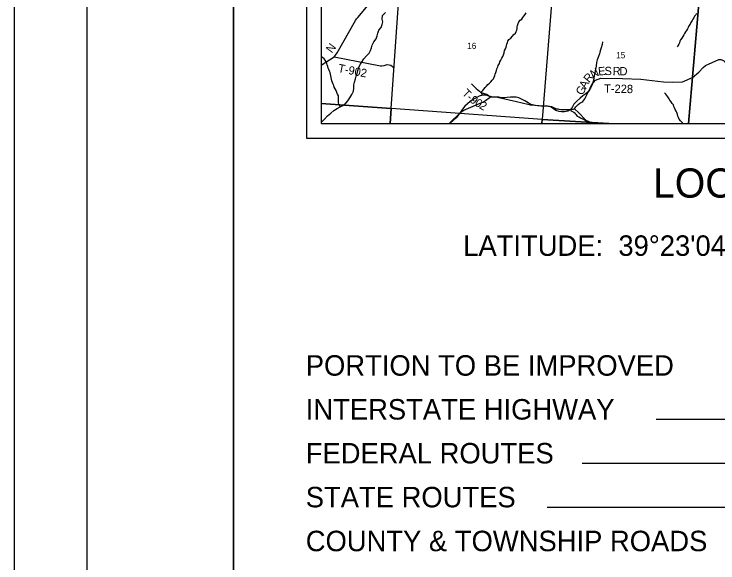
# Model space of a CAD drawing. Extents: x -13.1 to 43.1, y 0 to 22.
# Drawn here: x 0 to 4.813, y 11.097 to 14.849 of the extents above; entities that cross this region are included whole.
import ezdxf

# ---------------------------------------------------------------- set-up
doc = ezdxf.new("R2010")
doc.units = 0
for name, color, linetype in [('GM_X_Corporation', 7, 'Continuous'), ('GM_X_County_Road', 7, 'Continuous'), ('GM_X_County_Road_Text', 7, 'Continuous'), ('GM_X_Minor_River', 7, 'Continuous'), ('GM_X_Section_Text', 7, 'Continuous'), ('GM_X_Township_Road', 7, 'Continuous'), ('GM_X_Township_Road_Text', 7, 'Continuous'), ('SH_Border', 7, 'Continuous'), ('SH_Data', 7, 'Continuous'), ('SH_Text', 7, 'Continuous')]:
    doc.layers.add(name, color=color, linetype=linetype)

msp = doc.modelspace()

# ---------------------------------------------------------------- linework, layer by layer
at = {"layer": 'GM_X_Corporation'}
for points in [[(7.0807, 20.9), (2.1, 20.9), (2.1, 14.1), (6.6193, 14.1), (6.6994, 15.2069), (6.7531, 15.956), (6.8236, 16.9075), (6.9509, 19.0179), (7.0108, 19.8446), (7.0164, 19.8954), (7.0617, 20.6133)], [(7.0804, 20.9), (2.1, 20.9), (2.1, 14.1), (6.619, 14.1), (6.6992, 15.2074), (6.7528, 15.9566), (6.8234, 16.908), (6.8365, 17.1257), (6.9507, 19.0184), (6.9616, 19.1692), (7.0106, 19.8452), (7.0162, 19.896), (7.0615, 20.6138)], [(2.1, 17.2152), (2.1, 14.1), (6.619, 14.1), (6.6992, 15.2074), (6.7528, 15.9566), (6.8234, 16.908), (4.4304, 17.0575), (3.8328, 17.0966), (2.8442, 17.1637), (2.1437, 17.2135)], [(2.1, 15.1883), (2.1, 14.2382), (2.5786, 14.2031), (2.6447, 15.1518)], [(2.6447, 15.1518), (3.6885, 15.0891), (3.6113, 14.1287), (2.5786, 14.2031)], [(4.0665, 14.1), (4.6107, 14.1), (4.6921, 15.0289), (3.6885, 15.0891), (3.6113, 14.1287)], [(4.6107, 14.1), (5.5941, 14.1), (5.6613, 14.9873), (4.6921, 15.0289)], [(2.1, 14.2382), (2.1, 14.1), (2.5718, 14.1), (2.5786, 14.2031)], [(2.5718, 14.1), (3.6092, 14.1), (3.6113, 14.1287), (2.5786, 14.2031)], [(3.6092, 14.1), (4.0665, 14.1), (3.6113, 14.1287)]]:
    msp.add_lwpolyline(points, close=True, dxfattribs=at)
at = {"layer": 'GM_X_County_Road'}
msp.add_lwpolyline([(2.1, 14.4999), (2.188, 14.5566), (2.1915, 14.5592), (2.1978, 14.5682), (2.2084, 14.5828), (2.3353, 14.8038), (2.342, 14.8155), (2.3498, 14.8244), (2.4327, 14.9227)], dxfattribs=at)
at = {"layer": 'GM_X_Minor_River'}
for points in [[(2.1, 14.107), (2.1006, 14.1077), (2.1198, 14.1281), (2.1427, 14.1531), (2.1649, 14.1719), (2.1855, 14.1893), (2.2099, 14.2044), (2.2305, 14.2141), (2.2488, 14.2247), (2.2679, 14.239), (2.2832, 14.2564), (2.2947, 14.2753), (2.3093, 14.2995), (2.3201, 14.3207), (2.324, 14.3412), (2.3226, 14.3647), (2.3273, 14.3829), (2.335, 14.4064), (2.3397, 14.4239), (2.3451, 14.4428), (2.3513, 14.4633), (2.3583, 14.4868), (2.3698, 14.5072), (2.3805, 14.5246), (2.3913, 14.5428), (2.4089, 14.5632), (2.428, 14.5806), (2.438, 14.6002), (2.4441, 14.6177), (2.4496, 14.6366), (2.4603, 14.6586), (2.4764, 14.6805), (2.4826, 14.7002), (2.4873, 14.7192), (2.4942, 14.7381), (2.5103, 14.7563), (2.518, 14.7775), (2.5204, 14.7949), (2.5167, 14.8147), (2.5191, 14.8397), (2.539, 14.8601)], [(3.2021, 14.2935), (3.1931, 14.3153), (3.205, 14.3254), (3.2131, 14.3352), (3.2212, 14.3461), (3.2304, 14.3558), (3.2401, 14.3671), (3.2505, 14.3776), (3.2601, 14.3866), (3.2701, 14.3963), (3.2778, 14.4061), (3.2825, 14.4167), (3.2876, 14.4284), (3.2904, 14.4386), (3.2947, 14.4499), (3.2994, 14.462), (3.3014, 14.4745), (3.3077, 14.4874), (3.3112, 14.498), (3.3182, 14.5112), (3.3226, 14.5229), (3.3276, 14.5334), (3.3354, 14.5463), (3.3412, 14.5583), (3.3456, 14.5712), (3.3503, 14.584), (3.3539, 14.5996), (3.3597, 14.6113), (3.3652, 14.6237), (3.3661, 14.634), (3.3693, 14.6442), (3.3728, 14.654), (3.3771, 14.6638), (3.3837, 14.6747), (3.3956, 14.6852), (3.4049, 14.6965), (3.4179, 14.7089), (3.4291, 14.7193), (3.4322, 14.7292), (3.4369, 14.7398), (3.4397, 14.7511), (3.441, 14.761), (3.4415, 14.7716), (3.4462, 14.7841), (3.4517, 14.7958), (3.4605, 14.8063), (3.4713, 14.8149), (3.4779, 14.8251), (3.4856, 14.8348), (3.4945, 14.8453), (3.5014, 14.8563)], [(4.6666, 14.8538), (4.6612, 14.844), (4.6535, 14.8343), (4.6477, 14.8241), (4.6418, 14.8143), (4.6356, 14.8045), (4.6283, 14.7917), (4.6224, 14.7807), (4.6139, 14.7679), (4.6088, 14.7574), (4.6038, 14.7475), (4.5972, 14.7366), (4.5914, 14.7268), (4.5844, 14.7163), (4.5789, 14.7061), (4.5731, 14.6948), (4.565, 14.6842), (4.5576, 14.6733), (4.5526, 14.6635), (4.5494, 14.6533), (4.5447, 14.6431), (4.5389, 14.6322), (4.535, 14.6227)], [(4.0246, 14.6591), (4.0207, 14.6409), (4.0137, 14.6189), (4.0083, 14.5977), (4.0029, 14.5772), (3.9967, 14.559), (3.9874, 14.537), (3.9835, 14.5181), (3.9796, 14.4923), (3.9749, 14.4718), (3.971, 14.4475), (3.967, 14.4263), (3.9639, 14.4089), (3.96, 14.3884), (3.9523, 14.3657), (3.9407, 14.3414), (3.9261, 14.3172), (3.9086, 14.3044), (3.888, 14.2901), (3.8704, 14.2735), (3.8467, 14.25), (3.8283, 14.2327), (3.8176, 14.2153), (3.8084, 14.1979), (3.7863, 14.1858), (3.7626, 14.1799), (3.7436, 14.18), (3.7262, 14.1839), (3.7049, 14.1893), (3.6875, 14.2015), (3.6678, 14.2138), (3.6465, 14.2192), (3.626, 14.2185), (3.6017, 14.2202), (3.5781, 14.2226), (3.5546, 14.2265), (3.5363, 14.2304), (3.5151, 14.2411), (3.4924, 14.2564), (3.4749, 14.2648), (3.4506, 14.2763), (3.4332, 14.2802), (3.4134, 14.2811), (3.3952, 14.2804), (3.3723, 14.2783), (3.3541, 14.2761), (3.3351, 14.2769), (3.3146, 14.2801), (3.2742, 14.2803), (3.2408, 14.2888), (3.2211, 14.2942), (3.2021, 14.2935), (3.1808, 14.2876), (3.1632, 14.2778), (3.1411, 14.2673), (3.1197, 14.2522), (3.1006, 14.2348), (3.0815, 14.2182), (3.0662, 14.1986), (3.0532, 14.1789), (3.0378, 14.16), (3.0218, 14.1404), (3.0042, 14.1237), (2.9828, 14.1041), (2.9786, 14.1)], [(2.2305, 14.2141), (2.2195, 14.2328), (2.2188, 14.2427), (2.2182, 14.2533), (2.2191, 14.2677), (2.2189, 14.2791), (2.2179, 14.2902), (2.2123, 14.3005), (2.2068, 14.3138), (2.2024, 14.3257), (2.1964, 14.3371), (2.1897, 14.3501), (2.1857, 14.3597), (2.1812, 14.3707), (2.1764, 14.3814), (2.172, 14.3914), (2.171, 14.4031), (2.1673, 14.4161), (2.1648, 14.4275), (2.1627, 14.4374), (2.1609, 14.4485), (2.1565, 14.4584), (2.1524, 14.4702), (2.1487, 14.4801), (2.1455, 14.4912), (2.1418, 14.5015), (2.1389, 14.5114), (2.1337, 14.5232), (2.1277, 14.5332), (2.1206, 14.5431), (2.1097, 14.5516), (2.1, 14.5605)], [(4.5743, 14.1), (4.5742, 14.1001), (4.5656, 14.1101), (4.5558, 14.1185), (4.548, 14.1297), (4.5424, 14.1419), (4.538, 14.1518), (4.5354, 14.1629), (4.5318, 14.1751), (4.527, 14.1846), (4.5214, 14.1957), (4.5162, 14.2079), (4.511, 14.2179), (4.5085, 14.2281), (4.5003, 14.2385), (4.4928, 14.2492), (4.4849, 14.2596), (4.4794, 14.2703), (4.4693, 14.2822), (4.4633, 14.2918), (4.4558, 14.3013), (4.4479, 14.3109), (4.4472, 14.3106)], [(3.8084, 14.1979), (3.8072, 14.1871), (3.8174, 14.182), (3.8272, 14.1777), (3.8374, 14.1715), (3.8415, 14.1612), (3.8501, 14.1508), (3.8622, 14.1457), (3.8739, 14.1391), (3.886, 14.1333), (3.8988, 14.1274), (3.9087, 14.1223), (3.9215, 14.118), (3.9344, 14.1125), (3.9479, 14.1002), (3.948, 14.1)]]:
    msp.add_lwpolyline(points, dxfattribs=at)
at = {"layer": 'GM_X_Township_Road'}
msp.add_line((3.9258, 14.1), (3.9086, 14.1225), dxfattribs=at)
for points in [[(2.188, 14.5566), (2.505, 14.4959), (2.5153, 14.4943), (2.5298, 14.4969), (2.5511, 14.5033), (2.5656, 14.5024), (2.5755, 14.5001), (2.5876, 14.4897), (2.599, 14.4805)], [(4.1607, 14.4075), (4.2866, 14.4047), (4.4406, 14.3863), (4.5029, 14.384), (4.5714, 14.3866), (4.6386, 14.4163), (4.6829, 14.451), (4.7124, 14.4846), (4.7273, 14.4967), (4.8181, 14.5372), (4.8333, 14.5394), (4.85, 14.5317), (4.8731, 14.5065), (4.8871, 14.4965), (4.9057, 14.4888), (4.9703, 14.4762), (4.9859, 14.4693), (5.018, 14.4395), (5.0434, 14.4154), (5.0506, 14.4111), (5.0711, 14.408), (5.1884, 14.4126), (5.199, 14.4144), (5.2197, 14.4443)], [(3.9019, 14.2683), (3.9273, 14.3198), (3.94, 14.3433), (3.9515, 14.3675), (3.9764, 14.3963), (4.0111, 14.4109), (4.1607, 14.4075)], [(3.127, 14.3713), (3.1592, 14.3411), (3.1834, 14.3208), (3.1925, 14.3124), (3.2001, 14.3097), (3.2146, 14.3066), (3.2305, 14.3019), (3.2415, 14.2954), (3.2578, 14.2812)], [(2.9756, 14.1), (3.054, 14.1771), (3.0632, 14.1855), (3.0758, 14.193), (3.1876, 14.2394), (3.2104, 14.2492), (3.2238, 14.2571), (3.2486, 14.2752), (3.2578, 14.2812)], [(3.2578, 14.2812), (3.2692, 14.2831), (3.2822, 14.2841), (3.3061, 14.2813), (3.4365, 14.2513), (3.5136, 14.2322), (3.5288, 14.2294), (3.6517, 14.2203), (3.6619, 14.2199), (3.6737, 14.2172), (3.6881, 14.211), (3.6991, 14.2049), (3.7067, 14.2018), (3.717, 14.2006), (3.7257, 14.1982), (3.7387, 14.1966), (3.795, 14.1971), (3.8205, 14.1988), (3.8226, 14.199)], [(3.8226, 14.199), (3.8258, 14.1992), (3.8323, 14.2014), (3.8411, 14.215), (3.8568, 14.2305), (3.8683, 14.2388), (3.8828, 14.2456), (3.89, 14.2512), (3.9019, 14.2683)], [(3.9086, 14.1225), (3.9049, 14.1272), (3.8618, 14.1739), (3.8323, 14.2014)]]:
    msp.add_lwpolyline(points, dxfattribs=at)
at = {"layer": 'SH_Border'}
for points in [[(0.5, 21.5), (1.5, 21.5), (1.5, 0.5), (0.5, 0.5)], [(1.5, 21.5), (33.5, 21.5), (33.5, 0.5), (1.5, 0.5)]]:
    msp.add_lwpolyline(points, close=True, dxfattribs=at)
at = {"layer": 'SH_Data'}
for p, q in [((2, 21), (2, 14)), ((2.1, 20.9), (2.1, 14.1)), ((2.1, 14.1), (8.9, 14.1)), ((2.1, 14.1), (2.1, 14.1)), ((2, 14), (9, 14)), ((7.7, 12.0767), (4.3895, 12.0767)), ((7.7, 11.7767), (3.8854, 11.7767)), ((7.7, 11.4767), (3.6448, 11.4767))]:
    msp.add_line(p, q, dxfattribs=at)
msp.add_lwpolyline([(0, 0), (34, 0), (34, 22), (0, 22)], close=True, dxfattribs=at)

# ---------------------------------------------------------------- texts
at = {"layer": 'GM_X_County_Road_Text'}
msp.add_text('N', height=0.0568, rotation=53.1432, dxfattribs=at).set_placement((2.173, 14.578))
at = {"layer": 'GM_X_Section_Text'}
for s, p in [('16', (3.0984, 14.6106)), ('15', (4.1167, 14.5469))]:
    msp.add_text(s, height=0.04186, rotation=0, dxfattribs=at).set_placement(p)
at = {"layer": 'GM_X_Township_Road_Text'}
for s, height, rotation, p in [('T-902', 0.05682, 348.9656, (2.2116, 14.4529)), ('E', 0.0568, 5.1971, (3.9958, 14.4283)), ('S', 0.0568, 359.2873, (4.0366, 14.4321)), ('R', 0.0568, 358.9189, (4.0923, 14.4313)), ('D', 0.0568, 358.918, (4.139, 14.4304)), ('R', 0.0568, 51.033, (3.9318, 14.3757)), ('N', 0.0568, 25.8743, (3.956, 14.408)), ('G', 0.0568, 63.6467, (3.8879, 14.2896)), ('A', 0.0568, 61.9849, (3.9099, 14.334)), ('T-228', 0.05682, 358.8763, (4.0335, 14.3119)), ('T', 0.0568, 315.3909, (3.0583, 14.3024)), ('-', 0.0568, 317.6513, (3.0903, 14.2708)), ('9', 0.0568, 322.3819, (3.1115, 14.2518)), ('0', 0.0568, 329.0685, (3.1452, 14.2264)), ('2', 0.0568, 329.9508, (3.176, 14.2079))]:
    msp.add_text(s, height=height, rotation=rotation, dxfattribs=at).set_placement(p)
at = {"layer": 'SH_Text'}
for s, height, p in [('LOCATION MAP', 0.2, (4.3691, 13.5938)), ('LATITUDE:  39°23\'04"     LONGITUDE:  82°45\'20"', 0.14, (3.071, 13.1959)), ('PORTION TO BE IMPROVED', 0.14, (1.9944, 12.3767)), ('INTERSTATE HIGHWAY', 0.14, (1.9944, 12.0767)), ('FEDERAL ROUTES', 0.14, (1.9944, 11.7767)), ('STATE ROUTES', 0.14, (1.9944, 11.4767)), ('COUNTY & TOWNSHIP ROADS', 0.14, (1.9944, 11.1767))]:
    msp.add_text(s, height=height, dxfattribs=at).set_placement(p)

doc.saveas('drawing.dxf')
